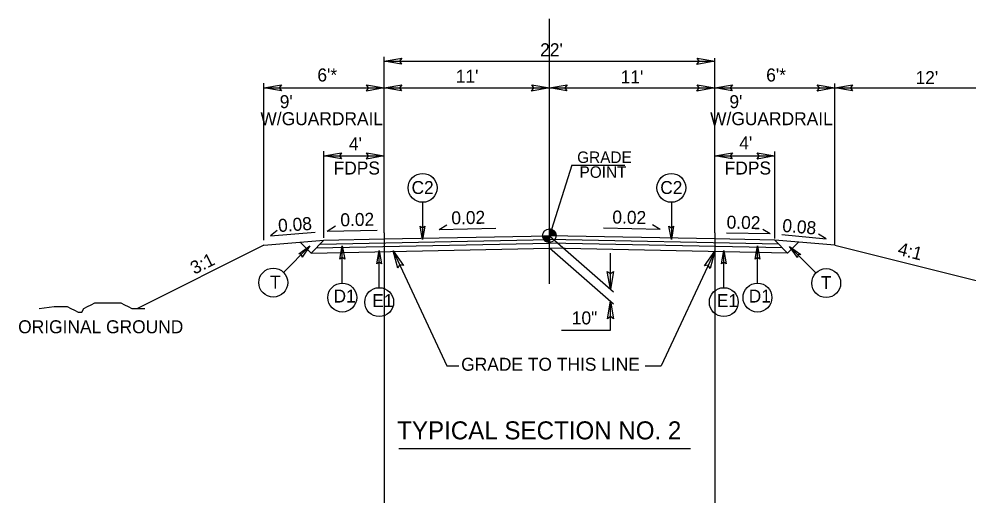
# Model space of a CAD drawing. Extents: x 1804008 to 1804260, y 659269 to 659379.
# Drawn here: x 1804135.5 to 1804198.7, y 659303.4 to 659335.1 of the extents above; entities that cross this region are included whole.
import ezdxf

# ---------------------------------------------------------------- set-up
doc = ezdxf.new("R2010")
doc.units = 0
for name, color, linetype in [('Old_Level_1', 7, 'Continuous'), ('Old_Level_21', 7, 'Continuous'), ('Old_Level_3', 7, 'Continuous'), ('Prop Dimension', 7, 'Continuous'), ('Prop Dimension Text', 7, 'Continuous'), ('Typical Berm Information CELL', 7, 'Continuous'), ('Typical Grade Point Symbol CELL', 7, 'Continuous'), ('Typical Hinge Slope Arterial CELL', 7, 'Continuous'), ('Typical ID Circle CELL', 7, 'Continuous'), ('Typical Pavement Slope Information CELL', 7, 'Continuous'), ('Typical Shoulder Slope Information CELL', 7, 'Continuous'), ('Typical Terminator CELL', 7, 'Continuous'), ('Typical Text General CELL', 7, 'Continuous'), ('Typical Text Grade Point CELL', 7, 'Continuous'), ('Typical Text ID Circle CELL', 7, 'Continuous')]:
    doc.layers.add(name, color=color, linetype=linetype)

msp = doc.modelspace()

# ---------------------------------------------------------------- linework, layer by layer
at = {"layer": 'Old_Level_1'}
for p, q in [((1804155.533, 659320.12), (1804170.79, 659320.425)), ((1804155.79, 659320.377), (1804159.79, 659320.459)), ((1804159.79, 659320.87), (1804159.79, 659289.984)), ((1804159.79, 659320.459), (1804170.79, 659320.679)), ((1804181.79, 659320.459), (1804170.79, 659320.679)), ((1804186.046, 659320.12), (1804170.79, 659320.425)), ((1804181.79, 659320.86), (1804181.79, 659290.502)), ((1804185.79, 659320.377), (1804181.79, 659320.459)), ((1804151.79, 659320.044), (1804155.79, 659320.377)), ((1804154.218, 659320.246), (1804154.938, 659319.525)), ((1804155.79, 659320.377), (1804154.938, 659319.525)), ((1804154.938, 659319.525), (1804170.801, 659319.842)), ((1804155.278, 659319.865), (1804170.795, 659320.175)), ((1804186.641, 659319.525), (1804170.778, 659319.842)), ((1804186.301, 659319.865), (1804170.785, 659320.175)), ((1804189.79, 659320.044), (1804185.79, 659320.377)), ((1804185.79, 659320.377), (1804186.641, 659319.525)), ((1804187.362, 659320.246), (1804186.641, 659319.525)), ((1804189.79, 659320.044), (1804201.79, 659317.044)), ((1804160.767, 659306.5), (1804180.183, 659306.5))]:
    msp.add_line(p, q, dxfattribs=at)
at = {"layer": 'Prop Dimension'}
for p, q in [((1804170.79, 659317.463), (1804170.79, 659335.108)), ((1804159.79, 659320.87), (1804159.79, 659332.599)), ((1804181.79, 659320.86), (1804181.79, 659332.495)), ((1804159.79, 659332.293), (1804181.79, 659332.293)), ((1804151.79, 659320.385), (1804151.79, 659330.824)), ((1804189.79, 659320.044), (1804189.79, 659330.815)), ((1804189.79, 659320.044), (1804189.79, 659330.815)), ((1804151.79, 659330.519), (1804159.79, 659330.519)), ((1804159.79, 659330.519), (1804170.79, 659330.519)), ((1804170.79, 659330.519), (1804181.79, 659330.519)), ((1804181.79, 659330.519), (1804189.79, 659330.519)), ((1804189.79, 659330.519), (1804201.79, 659330.519)), ((1804155.79, 659320.527), (1804155.79, 659326.297)), ((1804185.79, 659320.496), (1804185.79, 659326.287)), ((1804155.79, 659325.991), (1804159.79, 659325.991)), ((1804181.79, 659325.991), (1804185.79, 659325.991)), ((1804172.275, 659325.364), (1804170.79, 659320.679)), ((1804172.275, 659325.364), (1804175.813, 659325.364)), ((1804155.994, 659320.983), (1804156.561, 659321.326)), ((1804163.461, 659321.094), (1804163.961, 659321.397)), ((1804163.461, 659321.094), (1804167.22, 659321.17)), ((1804178.157, 659321.094), (1804174.397, 659321.17)), ((1804178.157, 659321.094), (1804177.657, 659321.397)), ((1804185.493, 659320.794), (1804184.993, 659321.096)), ((1804152.668, 659321.02), (1804152.234, 659320.668)), ((1804152.234, 659320.668), (1804155.198, 659320.914)), ((1804155.994, 659320.983), (1804159.341, 659321.05)), ((1804170.79, 659320.679), (1804175.05, 659316.95)), ((1804185.493, 659320.794), (1804182.577, 659320.852)), ((1804186.248, 659320.749), (1804189.208, 659320.469)), ((1804189.208, 659320.469), (1804188.708, 659320.771)), ((1804170.79, 659319.876), (1804175.05, 659316.147)), ((1804160.391, 659319.668), (1804163.968, 659312.002)), ((1804174.853, 659317.123), (1804174.853, 659319.522)), ((1804181.8, 659319.656), (1804178.229, 659312.002)), ((1804174.853, 659314.387), (1804174.853, 659316.32)), ((1804171.589, 659314.387), (1804174.853, 659314.387)), ((1804163.968, 659312.002), (1804164.764, 659312.002)), ((1804177.157, 659312.002), (1804178.229, 659312.002))]:
    msp.add_line(p, q, dxfattribs=at)
at = {"layer": 'Typical Grade Point Symbol CELL'}
for p, q in [((1804170.79, 659320.679), (1804170.79, 659321.126)), ((1804170.342, 659320.679), (1804170.79, 659320.679)), ((1804170.789, 659320.231), (1804170.79, 659320.679)), ((1804170.79, 659320.679), (1804170.789, 659320.231)), ((1804171.237, 659320.679), (1804170.79, 659320.679))]:
    msp.add_line(p, q, dxfattribs=at)
for points in [[(1804170.794, 659321.126), (1804170.794, 659321.126), (1804170.794, 659320.679)], [(1804170.803, 659321.126), (1804170.803, 659320.679)], [(1804170.812, 659321.125), (1804170.812, 659320.679)], [(1804170.82, 659321.125), (1804170.82, 659320.679)], [(1804170.829, 659321.124), (1804170.829, 659320.679)], [(1804170.838, 659321.123), (1804170.838, 659320.679)], [(1804170.847, 659321.122), (1804170.847, 659320.679)], [(1804170.856, 659321.121), (1804170.856, 659320.679)], [(1804170.865, 659321.12), (1804170.865, 659320.679)], [(1804170.874, 659321.118), (1804170.874, 659320.679)], [(1804170.883, 659321.116), (1804170.883, 659320.679)], [(1804170.892, 659321.114), (1804170.892, 659320.679)], [(1804170.901, 659321.112), (1804170.901, 659320.679)], [(1804170.91, 659321.109), (1804170.91, 659320.679)], [(1804170.919, 659321.107), (1804170.919, 659320.679)], [(1804170.928, 659321.104), (1804170.928, 659320.679)], [(1804170.937, 659321.101), (1804170.937, 659320.679)], [(1804170.946, 659321.098), (1804170.946, 659320.679)], [(1804170.955, 659321.094), (1804170.955, 659320.679)], [(1804170.964, 659321.091), (1804170.964, 659320.679)], [(1804170.973, 659321.086), (1804170.973, 659320.679)], [(1804170.982, 659321.083), (1804170.982, 659320.679)], [(1804170.991, 659321.079), (1804170.991, 659320.679)], [(1804170.999, 659321.074), (1804170.999, 659320.679)], [(1804171.008, 659321.069), (1804171.008, 659320.679)], [(1804171.017, 659321.064), (1804171.017, 659320.679)], [(1804171.026, 659321.059), (1804171.026, 659320.679)], [(1804171.035, 659321.053), (1804171.035, 659320.679)], [(1804170.344, 659320.679), (1804170.344, 659320.63)], [(1804170.353, 659320.679), (1804170.353, 659320.577)], [(1804170.362, 659320.679), (1804170.362, 659320.545)], [(1804170.371, 659320.679), (1804170.371, 659320.519)], [(1804170.38, 659320.679), (1804170.38, 659320.498)], [(1804170.389, 659320.679), (1804170.389, 659320.479)], [(1804170.398, 659320.679), (1804170.398, 659320.462)], [(1804170.407, 659320.679), (1804170.407, 659320.446)], [(1804170.416, 659320.679), (1804170.416, 659320.432)], [(1804170.425, 659320.679), (1804170.425, 659320.419)], [(1804170.434, 659320.679), (1804170.434, 659320.407)], [(1804170.442, 659320.679), (1804170.442, 659320.396)], [(1804170.451, 659320.679), (1804170.451, 659320.385)], [(1804170.46, 659320.679), (1804170.46, 659320.375)], [(1804170.469, 659320.679), (1804170.469, 659320.365)], [(1804170.478, 659320.679), (1804170.478, 659320.356)], [(1804170.487, 659320.679), (1804170.487, 659320.348)], [(1804170.496, 659320.679), (1804170.496, 659320.341)], [(1804170.505, 659320.679), (1804170.505, 659320.333)], [(1804170.514, 659320.679), (1804170.514, 659320.326)], [(1804170.523, 659320.679), (1804170.523, 659320.319)], [(1804170.532, 659320.679), (1804170.532, 659320.313)], [(1804170.541, 659320.679), (1804170.541, 659320.307)], [(1804170.55, 659320.679), (1804170.55, 659320.301)], [(1804170.559, 659320.679), (1804170.559, 659320.295)], [(1804170.568, 659320.679), (1804170.568, 659320.29)], [(1804170.577, 659320.679), (1804170.577, 659320.285)], [(1804170.586, 659320.679), (1804170.586, 659320.28)], [(1804170.595, 659320.679), (1804170.595, 659320.276)], [(1804170.604, 659320.679), (1804170.604, 659320.272)], [(1804170.613, 659320.679), (1804170.613, 659320.268)], [(1804170.622, 659320.679), (1804170.622, 659320.264)], [(1804170.63, 659320.679), (1804170.63, 659320.26)], [(1804170.639, 659320.679), (1804170.639, 659320.257)], [(1804170.648, 659320.679), (1804170.648, 659320.254)], [(1804170.657, 659320.679), (1804170.657, 659320.251)], [(1804170.666, 659320.679), (1804170.666, 659320.249)], [(1804170.675, 659320.679), (1804170.675, 659320.246)], [(1804170.684, 659320.679), (1804170.684, 659320.244)], [(1804170.693, 659320.679), (1804170.693, 659320.242)], [(1804170.702, 659320.679), (1804170.702, 659320.24)], [(1804170.711, 659320.679), (1804170.711, 659320.238)], [(1804170.72, 659320.679), (1804170.72, 659320.237)], [(1804170.729, 659320.679), (1804170.729, 659320.235)], [(1804170.738, 659320.679), (1804170.738, 659320.234)], [(1804170.747, 659320.679), (1804170.747, 659320.233)], [(1804170.756, 659320.679), (1804170.756, 659320.232)], [(1804170.765, 659320.679), (1804170.765, 659320.232)], [(1804170.774, 659320.679), (1804170.774, 659320.231)], [(1804170.783, 659320.679), (1804170.783, 659320.231), (1804170.783, 659320.231)], [(1804171.044, 659321.047), (1804171.044, 659320.679)], [(1804171.053, 659321.04), (1804171.053, 659320.679)], [(1804171.062, 659321.034), (1804171.062, 659320.679)], [(1804171.071, 659321.027), (1804171.071, 659320.679)], [(1804171.08, 659321.019), (1804171.08, 659320.679)], [(1804171.089, 659321.011), (1804171.089, 659320.679)], [(1804171.098, 659321.003), (1804171.098, 659320.679)], [(1804171.107, 659320.994), (1804171.107, 659320.679)], [(1804171.116, 659320.985), (1804171.116, 659320.679)], [(1804171.125, 659320.975), (1804171.125, 659320.679)], [(1804171.134, 659320.964), (1804171.134, 659320.679)], [(1804171.143, 659320.953), (1804171.143, 659320.679)], [(1804171.152, 659320.941), (1804171.152, 659320.679)], [(1804171.161, 659320.928), (1804171.161, 659320.679)], [(1804171.17, 659320.914), (1804171.17, 659320.679)], [(1804171.179, 659320.9), (1804171.179, 659320.679)], [(1804171.187, 659320.884), (1804171.187, 659320.679)], [(1804171.196, 659320.865), (1804171.196, 659320.679)], [(1804171.205, 659320.844), (1804171.205, 659320.679)], [(1804171.214, 659320.819), (1804171.214, 659320.679)], [(1804171.223, 659320.788), (1804171.223, 659320.679)], [(1804171.232, 659320.742), (1804171.232, 659320.679)]]:
    msp.add_lwpolyline(points, dxfattribs=at)
msp.add_circle((1804170.789, 659320.679), 0.448, dxfattribs=at)
for start, end in [(359.99048, 89.99048), (179.99048, 269.99048)]:
    msp.add_arc((1804170.789, 659320.679), 0.448, start, end, dxfattribs=at)
at = {"layer": 'Typical Hinge Slope Arterial CELL'}
msp.add_line((1804151.79, 659320.044), (1804143.376, 659315.837), dxfattribs=at)
msp.add_lwpolyline([(1804136.845, 659315.837), (1804137.83, 659315.959), (1804138.077, 659315.959), (1804138.447, 659315.959), (1804138.693, 659315.959), (1804138.94, 659315.837), (1804139.186, 659315.713), (1804139.432, 659315.589), (1804139.679, 659315.589), (1804139.803, 659315.837), (1804140.049, 659315.959), (1804140.295, 659316.083), (1804140.542, 659316.206), (1804140.788, 659316.206), (1804141.035, 659316.206), (1804141.281, 659316.206), (1804141.527, 659316.206), (1804141.774, 659316.206), (1804142.02, 659316.206), (1804142.267, 659316.206), (1804142.513, 659316.083), (1804142.759, 659315.959), (1804143.006, 659315.837), (1804143.376, 659315.837), (1804143.622, 659315.837), (1804143.869, 659315.837)], dxfattribs=at)
at = {"layer": 'Typical ID Circle CELL'}
for p, q in [((1804162.357, 659322.901), (1804162.357, 659320.416)), ((1804178.906, 659322.901), (1804178.906, 659320.416)), ((1804153.097, 659318.235), (1804154.856, 659319.993)), ((1804157.012, 659317.519), (1804157.012, 659320.004)), ((1804184.638, 659317.519), (1804184.638, 659320.004)), ((1804188.532, 659318.201), (1804186.773, 659319.958)), ((1804159.467, 659317.216), (1804159.467, 659319.702)), ((1804182.399, 659317.216), (1804182.399, 659319.702))]:
    msp.add_line(p, q, dxfattribs=at)
for centre in [(1804162.357, 659323.862), (1804178.906, 659323.862), (1804152.418, 659317.555), (1804189.211, 659317.521), (1804157.012, 659316.557), (1804184.638, 659316.557), (1804159.467, 659316.255), (1804182.399, 659316.255)]:
    msp.add_circle(centre, 0.962, dxfattribs=at)
at = {"layer": 'Typical Terminator CELL'}
for points in [[(1804160.961, 659332.091), (1804159.79, 659332.293), (1804160.968, 659332.501), (1804160.818, 659332.293)], [(1804180.618, 659332.495), (1804181.79, 659332.293), (1804180.611, 659332.085), (1804180.761, 659332.293)], [(1804152.961, 659330.317), (1804151.79, 659330.519), (1804152.968, 659330.727), (1804152.818, 659330.519)], [(1804158.618, 659330.72), (1804159.79, 659330.519), (1804158.611, 659330.31), (1804158.761, 659330.519)], [(1804160.961, 659330.317), (1804159.79, 659330.519), (1804160.968, 659330.727), (1804160.818, 659330.519)], [(1804169.618, 659330.72), (1804170.79, 659330.519), (1804169.611, 659330.31), (1804169.761, 659330.519)], [(1804171.961, 659330.317), (1804170.79, 659330.519), (1804171.968, 659330.727), (1804171.818, 659330.519)], [(1804171.961, 659330.317), (1804170.79, 659330.519), (1804171.968, 659330.727), (1804171.818, 659330.519)], [(1804180.618, 659330.72), (1804181.79, 659330.519), (1804180.611, 659330.31), (1804180.761, 659330.519)], [(1804182.961, 659330.317), (1804181.79, 659330.519), (1804182.968, 659330.727), (1804182.818, 659330.519)], [(1804188.618, 659330.72), (1804189.79, 659330.519), (1804188.611, 659330.31), (1804188.761, 659330.519)], [(1804190.961, 659330.317), (1804189.79, 659330.519), (1804190.968, 659330.727), (1804190.818, 659330.519)], [(1804156.961, 659325.789), (1804155.79, 659325.991), (1804156.968, 659326.199), (1804156.818, 659325.991)], [(1804158.618, 659326.193), (1804159.79, 659325.991), (1804158.611, 659325.783), (1804158.761, 659325.991)], [(1804182.961, 659325.789), (1804181.79, 659325.991), (1804182.968, 659326.199), (1804182.818, 659325.991)], [(1804184.618, 659326.193), (1804185.79, 659325.991), (1804184.611, 659325.783), (1804184.761, 659325.991)], [(1804162.51, 659321.306), (1804162.357, 659320.416), (1804162.199, 659321.311), (1804162.357, 659321.197)], [(1804179.059, 659321.306), (1804178.906, 659320.416), (1804178.748, 659321.311), (1804178.906, 659321.197)], [(1804154.117, 659319.472), (1804154.856, 659319.993), (1804154.334, 659319.248), (1804154.303, 659319.44)], [(1804156.858, 659319.114), (1804157.012, 659320.004), (1804157.17, 659319.109), (1804157.012, 659319.223)], [(1804184.485, 659319.114), (1804184.638, 659320.004), (1804184.796, 659319.109), (1804184.638, 659319.223)], [(1804187.295, 659319.22), (1804186.773, 659319.958), (1804187.519, 659319.437), (1804187.326, 659319.406)], [(1804159.314, 659318.811), (1804159.467, 659319.702), (1804159.626, 659318.806), (1804159.467, 659318.92)], [(1804160.703, 659318.521), (1804160.391, 659319.668), (1804161.078, 659318.689), (1804160.826, 659318.736)], [(1804181.122, 659318.68), (1804181.8, 659319.656), (1804181.491, 659318.5), (1804181.366, 659318.724)], [(1804182.246, 659318.811), (1804182.399, 659319.702), (1804182.558, 659318.806), (1804182.399, 659318.92)], [(1804175.055, 659318.294), (1804174.853, 659317.123), (1804174.645, 659318.301), (1804174.853, 659318.151)], [(1804174.651, 659315.148), (1804174.853, 659316.32), (1804175.061, 659315.142), (1804174.853, 659315.292)]]:
    msp.add_lwpolyline(points, close=True, dxfattribs=at)

# ---------------------------------------------------------------- texts
at = {"layer": 'Old_Level_21'}
msp.add_text('10"', height=0.865, dxfattribs=at).set_placement((1804172.281, 659314.772))
at = {"layer": 'Old_Level_3'}
msp.add_text('TYPICAL SECTION NO. 2', height=1.2, dxfattribs=at).set_placement((1804160.666, 659307.115))
at = {"layer": 'Prop Dimension Text'}
for s, p in [("22'", (1804170.177, 659332.627)), ("6'*", (1804155.353, 659330.947)), ("6'*", (1804185.218, 659330.947)), ("11'", (1804164.564, 659330.859)), ("11'", (1804175.533, 659330.815)), ("12'", (1804195.155, 659330.771)), ("     9'", (1804151.241, 659329.171)), ("     9'", (1804181.164, 659329.171)), (' W/GUARDRAIL ', (1804151.241, 659328.037)), (' W/GUARDRAIL ', (1804181.164, 659328.037)), ("4'", (1804157.45, 659326.368)), ("4'", (1804183.424, 659326.423)), ('FDPS', (1804156.433, 659324.752)), ('FDPS', (1804182.456, 659324.752))]:
    msp.add_text(s, height=0.865, dxfattribs=at).set_placement(p)
at = {"layer": 'Typical Berm Information CELL'}
for rotation, p in [(3.99898, (1804152.769, 659320.916)), (355.28797, (1804186.266, 659320.939))]:
    msp.add_text('0.08', height=0.865, rotation=rotation, dxfattribs=at).set_placement(p)
at = {"layer": 'Typical Hinge Slope Arterial CELL'}
for s, rotation, p in [('4:1', 345.96376, (1804193.918, 659319.417)), ('3:1', 26.56505, (1804147.171, 659318.075))]:
    msp.add_text(s, height=0.865, rotation=rotation, dxfattribs=at).set_placement(p)
msp.add_text('ORIGINAL GROUND', height=0.865, dxfattribs=at).set_placement((1804135.443, 659314.182))
at = {"layer": 'Typical Pavement Slope Information CELL'}
for rotation, p in [(1.14574, (1804164.276, 659321.429)), (358.85426, (1804174.974, 659321.493))]:
    msp.add_text('0.02', height=0.865, rotation=rotation, dxfattribs=at).set_placement(p)
at = {"layer": 'Typical Shoulder Slope Information CELL'}
for rotation, p in [(1.14574, (1804156.89, 659321.299)), (358.85426, (1804182.577, 659321.151))]:
    msp.add_text('0.02', height=0.865, rotation=rotation, dxfattribs=at).set_placement(p)
at = {"layer": 'Typical Text General CELL'}
msp.add_text('GRADE TO THIS LINE', height=0.865, dxfattribs=at).set_placement((1804164.922, 659311.684))
at = {"layer": 'Typical Text Grade Point CELL'}
for s, p in [('GRADE', (1804172.639, 659325.52)), ('POINT', (1804172.797, 659324.532))]:
    msp.add_text(s, height=0.765, dxfattribs=at).set_placement(p)
at = {"layer": 'Typical Text ID Circle CELL'}
for s, height, p in [('C2', 0.8608, (1804161.62, 659323.456)), ('C2', 0.8608, (1804178.169, 659323.456)), ('T', 0.861, (1804152.204, 659317.159)), ('T', 0.861, (1804188.859, 659317.125)), ('D1', 0.8608, (1804156.431, 659316.228)), ('E1', 0.8608, (1804159.004, 659315.925)), ('E1', 0.8608, (1804181.936, 659315.925)), ('D1', 0.8608, (1804184.058, 659316.228))]:
    msp.add_text(s, height=height, dxfattribs=at).set_placement(p)

doc.saveas('drawing.dxf')
